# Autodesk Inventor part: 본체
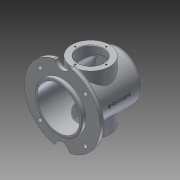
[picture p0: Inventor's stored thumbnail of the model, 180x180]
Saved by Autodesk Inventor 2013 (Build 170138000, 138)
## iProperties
Created: 2018-04
Part Number: 본체
Material: 알루미늄 6061
Document SubType Name: Modeling
Designer: Administrator
Density: 2.71 g/cm^3
Mass: 1150.05 g
Surface Area: 1203.2 cm^2
Volume: 424.372 cm^3
Author: Administrator
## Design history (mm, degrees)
sketch "스케치1"
  geometry: C1 r 50 at (0, 0); 1 further point
  constraints: 1 centre point, 1 coincident
  dimensions: "d0" = 100 diameter of C1
extrude "돌출1" new body sketch "스케치1" distance "d2" = 128; taper "d3" = 0 deg
node "작업 평면1"
sketch "스케치2"
  geometry: C1 r 45 at (0, 0); 1 further point
  constraints: 1 centre point, 1 coincident
  dimensions: "d5" = 90 diameter of C1
extrude "돌출2" cut sketch "스케치2" stored distance "d7" = 128; taper "d8" = 0 deg
fillet "모깎기1" dims "d9" = 5
fillet "모깎기2" dims "d10" = 3
sketch "스케치3"
  geometry: C1 r 45 at (0, 0) reference; C2 r 40 at (0, 0)
  constraints: 1 centre point, 1 coincident
  dimensions: "d11" = 80 diameter of C2
extrude "돌출3" join sketch "스케치3" distance "d13" = 5; taper "d14" = 0 deg
fillet "모깎기3" dims "d15" = 3
hole "구멍1" diameter "d18" = 54; stored, may be unused: countersink angle "d22" = 90 deg, drill point angle "d24" = 118 deg; dims "d16" = 10, "d17" = 10, "d19" = 6, "d20" = 4, "d21" = 2, "d23" = 8
sketch "스케치4"
  geometry: C1 r 27 at (0, 0) reference; 1 further point
  constraints: 1 horizontal alignment
  dimensions: "d25" = 32.5 distance of C1.centre point (32.5, 0)
hole "구멍2" sketch "스케치4" at (32.5, 0) diameter "d26" = 3.242; stored, may be unused: countersink angle "d30" = 90 deg, drill point angle "d32" = 118 deg; dims "d27" = 8, "d28" = 4, "d29" = 2, "d31" = 10
node "작업 평면2"
sketch "스케치5"
  geometry: C1 r 40 at (0, 68); 1 further point
  constraints: 1 centre point, 1 vertical alignment
  dimensions: "d37" = 68 distance of point (0, 0) C1.centre; "d38" = 80 diameter of C1
extrude "돌출4" join sketch "스케치5" stored distance "d39" = 5; taper "d40" = 0 deg
hole "구멍3" diameter "d43" = 54; stored, may be unused: countersink angle "d47" = 90 deg, drill point angle "d49" = 118 deg; dims "d41" = 10, "d42" = 10, "d44" = 8, "d45" = 4, "d46" = 2, "d48" = 10
sketch "스케치6"
  geometry: C1 r 27 at (0, 0) reference; 2 further points
  constraints: 1 vertical alignment
  dimensions: "d50" = 32.5 distance of C1.centre point (0, 32.5)
hole "구멍4" sketch "스케치6" at (0, 32.5) diameter "d51" = 3.242; stored, may be unused: countersink angle "d55" = 90 deg, drill point angle "d57" = 118 deg; dims "d52" = 8, "d53" = 4, "d54" = 2, "d56" = 10
sketch "스케치7"
  geometry: C1 r 27 at (0, 0) reference; 2 further points
  constraints: 1 vertical alignment
  dimensions: "d61" = 32.5 distance of C1.centre point (0, 32.5)
hole "구멍5" sketch "스케치7" at (0, 32.5) diameter "d62" = 3.242; stored, may be unused: countersink angle "d66" = 90 deg, drill point angle "d68" = 118 deg; dims "d63" = 8, "d64" = 4, "d65" = 2, "d67" = 10
chamfer "모따기1" distance "d72" = 1; stored, may be unused: second distance "d73" = 2, angle "d74" = 45 deg
chamfer "모따기2" distance "d75" = 1; stored, may be unused: second distance "d76" = 2, angle "d77" = 45 deg
fillet "모깎기4" dims "d78" = 3
fillet "모깎기5" dims "d79" = 3
node "작업 평면3"
sketch "스케치8"
  geometry: C1 r 80 at (0, 0); 1 further point
  constraints: 1 centre point, 1 coincident
  dimensions: "d81" = 160 diameter of C1
extrude "돌출5" join sketch "스케치8" distance "d83" = 10; taper "d84" = 0 deg
sketch "스케치9"
  geometry: C1 r 15 at (0, 80); 1 further point
  constraints: 2 vertical alignment, 1 centre point, 1 other
  dimensions: "d85" = 30 diameter of C1
extrude "돌출6" cut sketch "스케치9" stored distance "d87" = 10; taper "d88" = 0 deg
sketch "스케치10"
  geometry: L1 (0, 0)-(47.73, 47.73); L2 (0, 0)-(80, 0); C1 r 50 at (0, 0) reference; C2 r 5 at (47.73, 47.73); A1 r 80 centre (0, 0) between (14.934, -78.594) and (14.934, 78.594) reference
  constraints: 4 end point, 1 centre point, 1 point on circle
  dimensions: "d89" = 10 diameter of C2; "d91" = 67.5 distance of A1.centre L1.end; "d92" = 45 deg angle of L1 L2
extrude "돌출7" cut sketch "스케치10" stored distance "d93" = 10; taper "d94" = 0 deg
fillet "모깎기6" dims "d98" = 3
fillet "모깎기7" dims "d99" = 3
fillet "모깎기8" dims "d100" = 3
node "작업 평면4"
sketch "스케치11"
  geometry: 2 further points
  constraints: 1 horizontal alignment, 1 other
  dimensions: "d102" = 78 distance of point (78, 0) point (0, 0)
feature "엠보싱1" sketch "스케치11" dims "d0" = 100, "d13" = 5, "d103" = 0.5, "d104" = 0
hole "구멍6" diameter "d107" = 90; stored, may be unused: countersink angle "d111" = 90 deg, drill point angle "d113" = 118 deg; dims "d105" = 10, "d106" = 10, "d108" = 8, "d109" = 4, "d110" = 2, "d112" = 10
node "솔리드1"
pattern_circular "원형 패턴1" dims angle "d34" = 360 deg
mirror "대칭1"
pattern_circular "원형 패턴2" dims angle "d59" = 360 deg
pattern_circular "원형 패턴3" dims angle "d70" = 360 deg
mirror "대칭2"
pattern_circular "원형 패턴4" dims angle "d96" = 360 deg
other parameters: "d36" = 62, "d80" = 8
